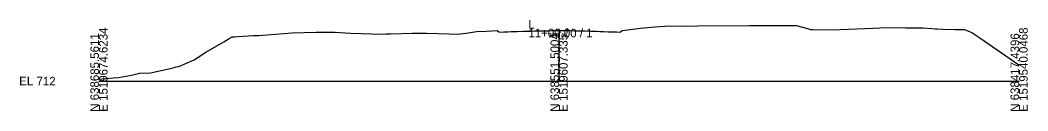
# Model space of a CAD drawing. Extents: x -26 to 3903, y -10 to 9531.
# Drawn here: x -25.7 to 302.8, y 990.3 to 1019.9 of the extents above; entities that cross this region are included whole.
import ezdxf

# ---------------------------------------------------------------- set-up
doc = ezdxf.new("R2010")
doc.units = 0
for name, color, linetype in [('Default', 7, 'Continuous'), ('Exist Cross Section Cell', 7, 'Continuous'), ('Exist XS Center Line Elevation Label', 7, 'Continuous'), ('Exist XS Ground Line', 7, 'Continuous')]:
    doc.layers.add(name, color=color, linetype=linetype)

msp = doc.modelspace()

# ---------------------------------------------------------------- linework, layer by layer
at = {"layer": 'Exist Cross Section Cell'}
for p, q in [((150, 1000), (150, 1017.08)), ((0, 1000), (150, 1000)), ((150, 1000), (300, 1000))]:
    msp.add_line(p, q, dxfattribs=at)
at = {"layer": 'Exist XS Ground Line'}
msp.add_lwpolyline([(0, 1000.69), (0.9, 1000.76), (2.37, 1000.87), (4.61, 1001.06), (6.41, 1001.13), (7.59, 1001.35), (10.04, 1001.78), (10.61, 1001.89), (12.83, 1002.5), (12.87, 1002.51), (13.23, 1002.56), (16.79, 1002.65), (22.74, 1004.03), (24.5, 1004.49), (25.19, 1004.63), (26.05, 1004.81), (31, 1006.95), (34.89, 1009.42), (40.67, 1012.81), (42.41, 1013.85), (43.48, 1014.42), (44.22, 1014.44), (45.33, 1014.57), (50.32, 1014.84), (52.13, 1014.92), (62.99, 1015.77), (70.83, 1016.01), (76.97, 1015.97), (81.96, 1015.65), (92.31, 1015.36), (93.67, 1015.41), (95.04, 1015.46), (102.26, 1015.59), (106.8, 1015.59), (114.14, 1015.41), (117.03, 1015.31), (120.52, 1015.79), (123.12, 1016.19), (126.34, 1016.33), (129.84, 1016.48), (130.21, 1016.18), (130.43, 1016), (132.03, 1016.06), (132.24, 1016.06), (132.62, 1016.07), (133.32, 1016.09), (134.44, 1016.13), (135.37, 1016.17), (136.37, 1016.2), (138.18, 1016.25), (138.95, 1016.28), (139.92, 1016.32), (140.49, 1016.32), (140.98, 1016.32), (141.99, 1016.35), (143.76, 1016.39), (145.51, 1016.42), (146.55, 1016.44), (147.6, 1016.45), (149.34, 1016.47), (149.74, 1016.48), (149.95, 1016.49), (150.72, 1016.48), (151.18, 1016.48), (152.15, 1016.47), (153.67, 1016.45), (154.96, 1016.43), (155.53, 1016.42), (156.66, 1016.39), (157.75, 1016.36), (158.52, 1016.35), (160, 1016.32), (160.11, 1016.33), (160.67, 1016.3), (162.22, 1016.25), (163.33, 1016.22), (164.45, 1016.18), (166.12, 1016.12), (166.61, 1016.1), (166.8, 1016.09), (167.7, 1016.06), (168.05, 1016.05), (168.72, 1016.04), (169.86, 1016.01), (170.47, 1016.43), (170.55, 1016.49), (170.68, 1016.51), (176.58, 1017.23), (181.36, 1017.7), (185.96, 1017.99), (190.52, 1017.96), (195.29, 1018.01), (212.09, 1018.16), (212.62, 1018.17), (213.07, 1018.17), (227.29, 1018.16), (231.05, 1017.16), (232.02, 1016.82), (232.66, 1016.85), (239.04, 1016.7), (241.62, 1016.78), (252.42, 1017.29), (256.75, 1017.52), (263.01, 1017.38), (268.64, 1017.41), (271.59, 1017.12), (272.68, 1017), (273.29, 1017), (275.14, 1016.91), (279.24, 1016.86), (282.21, 1016.83), (284.07, 1016.05), (284.58, 1015.9), (287.18, 1014.09), (299.87, 1005.3), (300, 1005.22)], dxfattribs=at)

# ---------------------------------------------------------------- texts
at = {"layer": 'Default'}
msp.add_text('-', height=0.0001, dxfattribs=at).set_placement((0, 1000))
at = {"layer": 'Exist Cross Section Cell'}
for s, p in [('L', (140, 1017.08)), ('11+00.00 / 1', (140, 1014.28)), ('EL 712', (-26, 998.6))]:
    msp.add_text(s, height=2.8, dxfattribs=at).set_placement(p)
for s, p in [('N 638685.5611', (0, 990)), ('E 1519674.6234', (2.8, 990)), ('N 638551.5004', (150, 990)), ('E 1519607.3351', (152.8, 990)), ('N 638417.4396', (300, 990)), ('E 1519540.0468', (302.8, 990))]:
    msp.add_text(s, height=2.8, rotation=90, dxfattribs=at).set_placement(p)
at = {"layer": 'Exist XS Center Line Elevation Label'}
msp.add_text('728.48', height=1.5, rotation=0.8401, dxfattribs=at).set_placement((146.48, 1014.15))

doc.saveas('drawing.dxf')
